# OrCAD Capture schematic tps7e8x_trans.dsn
size A; title: TPS7E8250 Transient Model; rev: 1; note: Datasheet: SLVSK53B
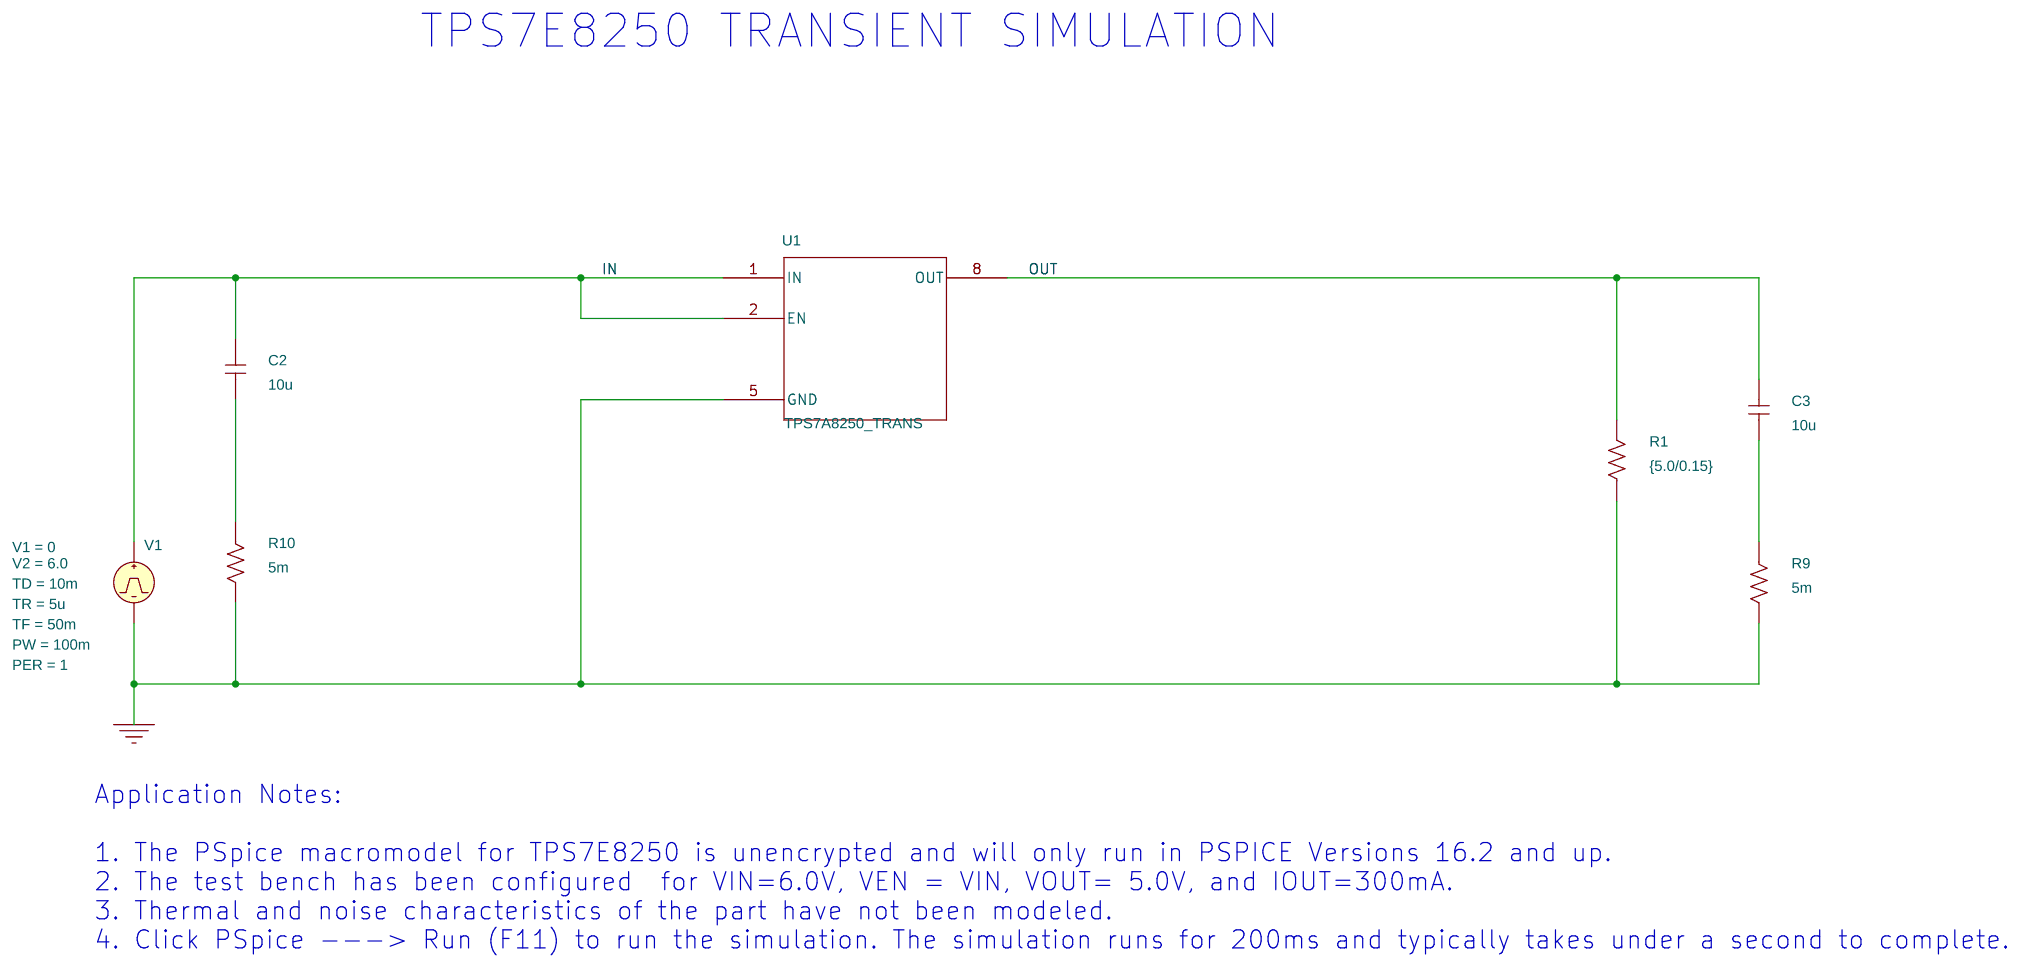
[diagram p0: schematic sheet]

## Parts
C2  10u  [RAD/CK05]
C3  10u  [RAD/CK05]
R1  {5.0/0.15}  [AX/RC05]
R9  5m  [AX/RC05]
R10  5m  [AX/RC05]
U1  TPS7A8250_TRANS
V1  VPULSE

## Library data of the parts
C2 C3 = C
R1 R9 R10 = R
U1 = TPS7E8250_TRANS
V1 = VPULSE: PER: 1; PW: 100m; TD: 10m; TF: 50m; TR: 5u; V1: 0; V2: 6.0

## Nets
0: R1.1 R9.2 R10.2 U1.5(GND) V1.2(-)
IN: C2.2 U1.1(IN) U1.2(EN) V1.1(+)
OUT: C3.2 R1.2 U1.8(OUT)
N944978: C2.1 R10.1
N945042: C3.1 R9.1

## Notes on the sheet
- TPS7E8250 TRANSIENT SIMULATION
- Application Notes:
  1. The PSpice macromodel for TPS7E8250 is unencrypted and will only run in PSPICE Versions 16.2 and up.
  2. The test bench has been configured  for VIN=6.0V, VEN = VIN, VOUT= 5.0V, and IOUT=300mA.
  3. Thermal and noise characteristics of the part have not been modeled.
  4. Click PSpice ---> Run (F11) to run the simulation. The simulation runs for 200ms and typically takes under a second to complete.
